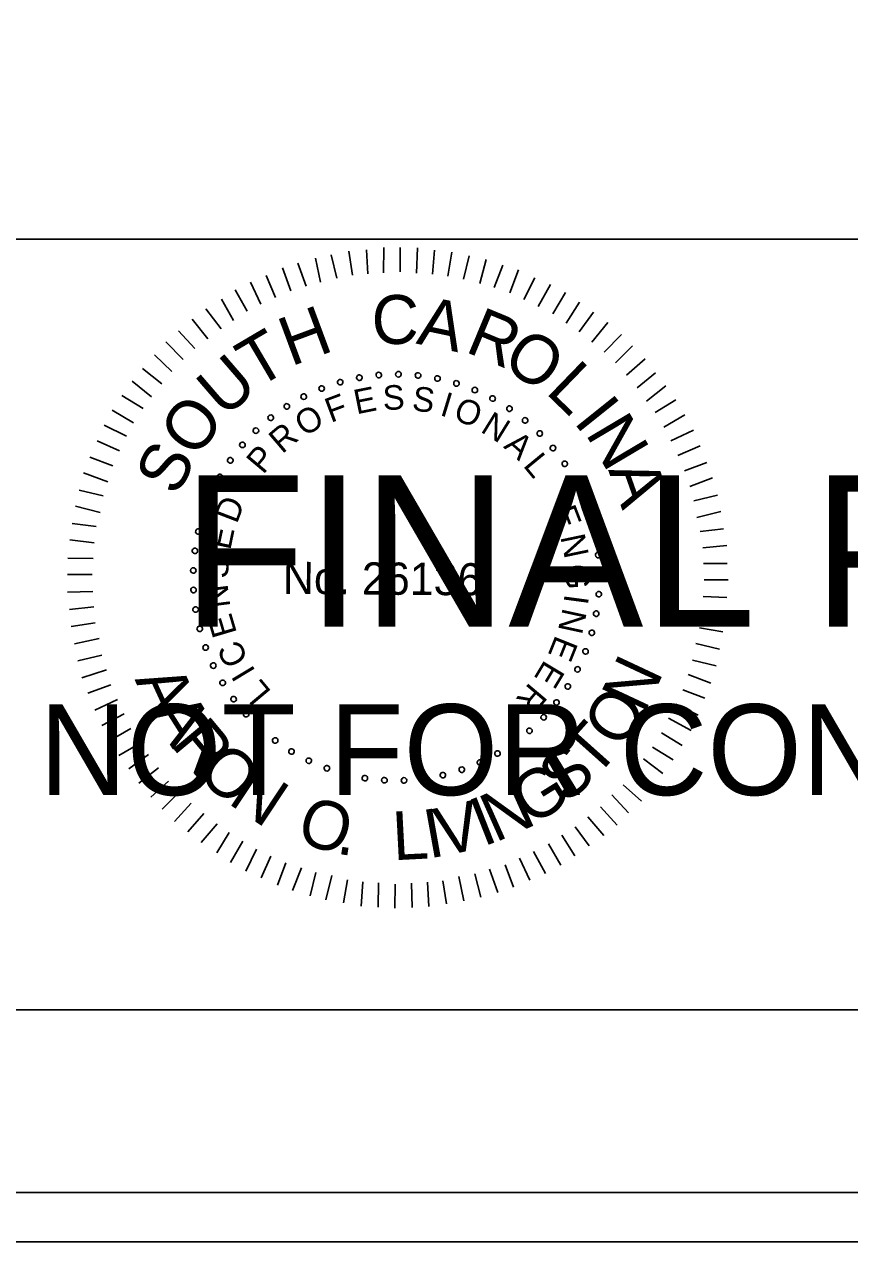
# Model space of a CAD drawing. Extents: x 967 to 1326, y 964 to 3144.
# Drawn here: x 1170.56 to 1189.3, y 1243.72 to 1271.36 of the extents above; entities that cross this region are included whole.
import ezdxf

# ---------------------------------------------------------------- set-up
doc = ezdxf.new("R2010")
doc.units = 0
for name, color, linetype in [('RD_SHT_Bndy', 7, 'Continuous'), ('RD_SHT_IplotShp', 7, 'Continuous'), ('RD_SHT_Misc1', 7, 'Continuous'), ('RD_SHT_Misc2', 7, 'Continuous'), ('RD_Sketch1', 7, 'Continuous')]:
    doc.layers.add(name, color=color, linetype=linetype)

msp = doc.modelspace()

# ---------------------------------------------------------------- linework, layer by layer
at = {"layer": 'RD_SHT_Bndy'}
for p, q in [((996.114, 1266.486), (1323.886, 1266.486)), ((1323.886, 1248.983), (996.114, 1248.983))]:
    msp.add_line(p, q, dxfattribs=at)
at = {"layer": 'RD_SHT_IplotShp'}
for points in [[(967.409, 1243.72), (1326.285, 1243.72), (1326.285, 1463.72), (967.409, 1463.72)], [(988.525, 1244.84), (1326.285, 1244.84), (1326.285, 1462.6), (988.525, 1462.6)]]:
    msp.add_lwpolyline(points, close=True, dxfattribs=at)
at = {"layer": 'RD_SHT_Misc1'}
for p, q in [((1178.01, 1265.663), (1177.93, 1266.209)), ((1178.364, 1265.699), (1178.33, 1266.244)), ((1178.717, 1265.719), (1178.722, 1266.295)), ((1179.093, 1265.739), (1179.098, 1266.292)), ((1179.469, 1265.713), (1179.489, 1266.288)), ((1179.829, 1265.687), (1179.872, 1266.231)), ((1180.174, 1265.646), (1180.271, 1266.19)), ((1176.964, 1265.419), (1176.769, 1265.935)), ((1177.287, 1265.508), (1177.169, 1266.054)), ((1177.657, 1265.597), (1177.53, 1266.128)), ((1180.535, 1265.573), (1180.662, 1266.102)), ((1180.902, 1265.478), (1181.045, 1266.022)), ((1176.264, 1265.156), (1176.053, 1265.657)), ((1176.61, 1265.306), (1176.423, 1265.83)), ((1181.231, 1265.384), (1181.428, 1265.896)), ((1181.584, 1265.265), (1181.78, 1265.786)), ((1175.933, 1265.005), (1175.699, 1265.506)), ((1181.905, 1265.109), (1182.154, 1265.606)), ((1182.226, 1264.953), (1182.506, 1265.45)), ((1175.308, 1264.634), (1175.036, 1265.12)), ((1175.624, 1264.846), (1175.352, 1265.332)), ((1182.562, 1264.789), (1182.85, 1265.27)), ((1175.03, 1264.445), (1174.681, 1264.9)), ((1182.86, 1264.572), (1183.163, 1265.053)), ((1183.158, 1264.378), (1183.484, 1264.828)), ((1174.729, 1264.217), (1174.372, 1264.665)), ((1183.447, 1264.145), (1183.811, 1264.587)), ((1174.435, 1263.997), (1174.062, 1264.399)), ((1183.729, 1263.92), (1184.116, 1264.316)), ((1174.172, 1263.753), (1173.776, 1264.148)), ((1183.98, 1263.672), (1184.368, 1264.061)), ((1173.909, 1263.479), (1173.52, 1263.858)), ((1184.232, 1263.394), (1184.657, 1263.767)), ((1173.684, 1263.197), (1173.242, 1263.546)), ((1184.475, 1263.108), (1184.892, 1263.45)), ((1173.451, 1262.9), (1173.009, 1263.256)), ((1184.687, 1262.807), (1185.128, 1263.156)), ((1173.257, 1262.64), (1172.776, 1262.936)), ((1173.039, 1262.312), (1172.559, 1262.6)), ((1184.885, 1262.544), (1185.355, 1262.832)), ((1185.081, 1262.213), (1185.56, 1262.493)), ((1172.883, 1262.006), (1172.379, 1262.256)), ((1185.24, 1261.904), (1185.756, 1262.145)), ((1172.727, 1261.677), (1172.215, 1261.904)), ((1185.399, 1261.573), (1185.907, 1261.791)), ((1172.571, 1261.333), (1172.051, 1261.53)), ((1185.549, 1261.226), (1186.057, 1261.414)), ((1172.461, 1260.974), (1171.91, 1261.178)), ((1185.669, 1260.865), (1186.185, 1261.06)), ((1172.351, 1260.652), (1171.807, 1260.787)), ((1185.759, 1260.541), (1186.297, 1260.667)), ((1172.286, 1260.276), (1171.727, 1260.419)), ((1185.832, 1260.165), (1186.371, 1260.298)), ((1172.191, 1259.955), (1171.647, 1260.029)), ((1185.906, 1259.842), (1186.436, 1259.906)), ((1172.15, 1259.587), (1171.598, 1259.653)), ((1185.964, 1259.473), (1186.51, 1259.53)), ((1172.124, 1259.234), (1171.548, 1259.239)), ((1185.977, 1259.12), (1186.514, 1259.115)), ((1172.105, 1258.866), (1171.545, 1258.871)), ((1185.997, 1258.751), (1186.542, 1258.747)), ((1172.118, 1258.482), (1171.542, 1258.471)), ((1185.971, 1258.368), (1186.508, 1258.348)), ((1172.138, 1258.136), (1171.585, 1258.072)), ((1185.952, 1258.022), (1186.497, 1257.949)), ((1172.173, 1257.768), (1171.627, 1257.688)), ((1185.888, 1257.655), (1186.417, 1257.566)), ((1172.262, 1257.414), (1171.701, 1257.296)), ((1185.808, 1257.302), (1186.345, 1257.175)), ((1172.321, 1257.037), (1171.774, 1256.911)), ((1185.729, 1256.926), (1186.265, 1256.792)), ((1172.425, 1256.707), (1171.871, 1256.519)), ((1185.634, 1256.597), (1186.146, 1256.401)), ((1172.53, 1256.36), (1172.007, 1256.173)), ((1185.508, 1256.253), (1186.013, 1256.057)), ((1172.681, 1256.029), (1172.165, 1255.788)), ((1172.831, 1255.705), (1172.323, 1255.441)), ((1185.352, 1255.924), (1185.857, 1255.675)), ((1185.188, 1255.603), (1185.7, 1255.33)), ((1172.982, 1255.374), (1172.497, 1255.094)), ((1185.024, 1255.274), (1185.498, 1254.987)), ((1173.194, 1255.042), (1172.709, 1254.762)), ((1184.822, 1254.946), (1185.288, 1254.658)), ((1173.384, 1254.78), (1172.936, 1254.453)), ((1184.62, 1254.687), (1185.055, 1254.353)), ((1173.612, 1254.478), (1173.164, 1254.129)), ((1184.403, 1254.389), (1184.814, 1254.033)), ((1173.832, 1254.177), (1173.437, 1253.812)), ((1184.155, 1254.092), (1184.574, 1253.72)), ((1174.091, 1253.945), (1173.689, 1253.541)), ((1183.899, 1253.864), (1184.28, 1253.454)), ((1174.35, 1253.674), (1173.97, 1253.263)), ((1183.644, 1253.597), (1184.024, 1253.18)), ((1174.64, 1253.442), (1174.275, 1253.022)), ((1174.937, 1253.209), (1174.58, 1252.782)), ((1183.358, 1253.37), (1183.715, 1252.944)), ((1175.212, 1253.014), (1174.932, 1252.549)), ((1182.764, 1252.952), (1183.059, 1252.482)), ((1183.065, 1253.141), (1183.384, 1252.709)), ((1175.525, 1252.812), (1175.245, 1252.331)), ((1182.463, 1252.755), (1182.743, 1252.269)), ((1175.83, 1252.633), (1175.588, 1252.136)), ((1176.159, 1252.477), (1175.94, 1251.98)), ((1181.8, 1252.431), (1182.041, 1251.93)), ((1182.124, 1252.581), (1182.396, 1252.08)), ((1176.503, 1252.321), (1176.307, 1251.816)), ((1176.855, 1252.211), (1176.651, 1251.69)), ((1177.177, 1252.1), (1177.05, 1251.572)), ((1181.122, 1252.175), (1181.31, 1251.652)), ((1181.476, 1252.28), (1181.664, 1251.771)), ((1177.545, 1252.036), (1177.409, 1251.484)), ((1177.897, 1251.933), (1177.808, 1251.412)), ((1178.25, 1251.892), (1178.207, 1251.34)), ((1178.603, 1251.866), (1178.598, 1251.313)), ((1178.978, 1251.84), (1178.974, 1251.295)), ((1179.355, 1251.86), (1179.365, 1251.307)), ((1179.715, 1251.88), (1179.749, 1251.327)), ((1180.061, 1251.915), (1180.149, 1251.393)), ((1180.423, 1252.012), (1180.541, 1251.458)), ((1180.791, 1252.07), (1180.926, 1251.54))]:
    msp.add_line(p, q, dxfattribs=at)
for centre, start, end in [((1178.609, 1263.397), 5.0653, 185.0653), ((1179.055, 1263.414), 359.5268, 179.5268), ((1179.055, 1263.414), 179.5268, 359.5268), ((1179.5, 1263.388), 353.9884, 173.9884), ((1177.312, 1263.091), 21.6807, 201.6807), ((1177.734, 1263.235), 16.1422, 196.1422), ((1177.734, 1263.235), 196.1422, 16.1422), ((1178.168, 1263.337), 10.6038, 190.6038), ((1178.168, 1263.337), 190.6038, 10.6038), ((1178.609, 1263.397), 185.0653, 5.0653), ((1179.5, 1263.388), 173.9884, 353.9884), ((1179.94, 1263.319), 168.4499, 348.4499), ((1179.94, 1263.319), 348.4499, 168.4499), ((1180.372, 1263.208), 162.9114, 342.9114), ((1180.372, 1263.208), 342.9114, 162.9114), ((1176.906, 1262.908), 27.2191, 207.2191), ((1176.906, 1262.908), 207.2191, 27.2191), ((1177.312, 1263.091), 201.6807, 21.6807), ((1180.79, 1263.056), 157.373, 337.373), ((1180.79, 1263.056), 337.373, 157.373), ((1181.193, 1262.864), 151.8345, 331.8345), ((1181.193, 1262.864), 331.8345, 151.8345), ((1176.52, 1262.686), 32.7576, 212.7576), ((1176.52, 1262.686), 212.7576, 32.7576), ((1181.574, 1262.634), 146.2961, 326.2961), ((1181.574, 1262.634), 326.2961, 146.2961), ((1176.156, 1262.428), 38.2961, 218.2961), ((1176.156, 1262.428), 218.2961, 38.2961), ((1181.932, 1262.368), 140.7576, 320.7576), ((1181.932, 1262.368), 320.7576, 140.7576), ((1175.82, 1262.135), 43.8345, 223.8345), ((1175.82, 1262.135), 223.8345, 43.8345), ((1182.263, 1262.069), 135.2191, 315.2191), ((1182.263, 1262.069), 315.2191, 135.2191), ((1175.513, 1261.812), 49.373, 229.373), ((1175.513, 1261.812), 229.373, 49.373), ((1182.563, 1261.74), 129.6807, 309.6807), ((1182.563, 1261.74), 309.6807, 129.6807), ((1175.239, 1261.461), 54.9114, 234.9114), ((1175.239, 1261.461), 234.9114, 54.9114), ((1182.83, 1261.383), 124.1422, 304.1422), ((1182.83, 1261.383), 304.1422, 124.1422), ((1175, 1261.085), 60.4499, 240.4499), ((1175, 1261.085), 240.4499, 60.4499), ((1183.061, 1261.002), 118.6038, 298.6038), ((1183.061, 1261.002), 298.6038, 118.6038), ((1174.798, 1260.687), 65.9884, 245.9884), ((1174.798, 1260.687), 245.9884, 65.9884), ((1183.255, 1260.601), 113.0653, 293.0653), ((1183.255, 1260.601), 293.0653, 113.0653), ((1174.636, 1260.272), 71.5268, 251.5268), ((1174.636, 1260.272), 251.5268, 71.5268), ((1183.408, 1260.182), 107.5268, 287.5268), ((1183.408, 1260.182), 287.5268, 107.5268), ((1174.514, 1259.843), 77.0653, 257.0653), ((1174.514, 1259.843), 257.0653, 77.0653), ((1183.521, 1259.751), 101.9884, 281.9884), ((1183.521, 1259.751), 281.9884, 101.9884), ((1174.435, 1259.405), 82.6038, 262.6038), ((1174.435, 1259.405), 262.6038, 82.6038), ((1183.592, 1259.311), 96.4499, 276.4499), ((1183.592, 1259.311), 276.4499, 96.4499), ((1174.398, 1258.961), 88.1422, 268.1422), ((1174.398, 1258.961), 268.1422, 88.1422), ((1183.619, 1258.866), 90.9114, 270.9114), ((1183.619, 1258.866), 270.9114, 90.9114), ((1174.404, 1258.515), 93.6807, 273.6807), ((1174.404, 1258.515), 273.6807, 93.6807), ((1183.604, 1258.421), 85.373, 265.373), ((1183.604, 1258.421), 265.373, 85.373), ((1174.453, 1258.072), 99.2191, 279.2191), ((1174.453, 1258.072), 279.2191, 99.2191), ((1183.546, 1257.979), 79.8345, 259.8345), ((1183.546, 1257.979), 259.8345, 79.8345), ((1174.545, 1257.636), 104.7576, 284.7576), ((1174.545, 1257.636), 284.7576, 104.7576), ((1183.445, 1257.545), 74.2961, 254.2961), ((1183.445, 1257.545), 254.2961, 74.2961), ((1174.678, 1257.211), 110.2961, 290.2961), ((1174.678, 1257.211), 290.2961, 110.2961), ((1183.303, 1257.122), 68.7576, 248.7576), ((1183.303, 1257.122), 248.7576, 68.7576), ((1174.852, 1256.8), 115.8345, 295.8345), ((1174.852, 1256.8), 295.8345, 115.8345), ((1183.121, 1256.716), 63.2191, 243.2191), ((1183.121, 1256.716), 243.2191, 63.2191), ((1175.065, 1256.409), 121.373, 301.373), ((1175.065, 1256.409), 301.373, 121.373), ((1182.9, 1256.328), 57.6807, 237.6807), ((1182.9, 1256.328), 237.6807, 57.6807), ((1175.314, 1256.039), 126.9114, 306.9114), ((1175.314, 1256.039), 306.9114, 126.9114), ((1182.643, 1255.964), 52.1422, 232.1422), ((1182.643, 1255.964), 232.1422, 52.1422), ((1175.598, 1255.696), 132.4499, 312.4499), ((1175.598, 1255.696), 312.4499, 132.4499), ((1182.353, 1255.627), 46.6038, 226.6038), ((1175.914, 1255.381), 137.9884, 317.9884), ((1175.914, 1255.381), 317.9884, 137.9884), ((1182.353, 1255.627), 226.6038, 46.6038), ((1176.258, 1255.099), 143.5268, 323.5268), ((1176.258, 1255.099), 323.5268, 143.5268), ((1182.03, 1255.319), 41.0653, 221.0653), ((1182.03, 1255.319), 221.0653, 41.0653), ((1176.629, 1254.851), 149.0653, 329.0653), ((1176.629, 1254.851), 329.0653, 149.0653), ((1181.305, 1254.803), 29.9884, 209.9884), ((1181.68, 1255.043), 35.5268, 215.5268), ((1181.68, 1255.043), 215.5268, 35.5268), ((1177.021, 1254.639), 154.6038, 334.6038), ((1177.021, 1254.639), 334.6038, 154.6038), ((1180.908, 1254.6), 24.4499, 204.4499), ((1180.908, 1254.6), 204.4499, 24.4499), ((1181.305, 1254.803), 209.9884, 29.9884), ((1177.432, 1254.467), 160.1422, 340.1422), ((1177.432, 1254.467), 340.1422, 160.1422), ((1177.858, 1254.335), 165.6807, 345.6807), ((1177.858, 1254.335), 345.6807, 165.6807), ((1178.294, 1254.245), 351.2191, 171.2191), ((1179.627, 1254.232), 7.8345, 187.8345), ((1180.065, 1254.313), 13.373, 193.373), ((1180.065, 1254.313), 193.373, 13.373), ((1180.494, 1254.436), 18.9114, 198.9114), ((1180.494, 1254.436), 198.9114, 18.9114), ((1178.294, 1254.245), 171.2191, 351.2191), ((1178.737, 1254.198), 356.7576, 176.7576), ((1178.737, 1254.198), 176.7576, 356.7576), ((1179.183, 1254.193), 2.2961, 182.2961), ((1179.183, 1254.193), 182.2961, 2.2961), ((1179.627, 1254.232), 187.8345, 7.8345)]:
    msp.add_arc(centre, 0.0627, start, end, dxfattribs=at)
at = {"layer": 'RD_Sketch1'}
msp.add_lwpolyline([(967.409, 1243.72), (1326.285, 1243.72), (1326.285, 1463.72), (967.409, 1463.72)], close=True, dxfattribs=at)

# ---------------------------------------------------------------- texts
at = {"layer": 'RD_SHT_Misc1'}
for s, height, rotation, p in [('C', 1.11, 359.5482, (1178.442, 1264.108)), ('A', 1.11, 348.1981, (1179.439, 1264.115)), ('H', 1.11, 20.3637, (1176.614, 1263.587)), ('R', 1.11, 337.4344, (1180.541, 1263.937)), ('T', 1.11, 30.4992, (1175.828, 1263.072)), ('O', 1.108, 326.5869, (1181.366, 1263.609)), ('U', 1.11, 40.8022, (1175.102, 1262.403)), ('L', 1.11, 315.9488, (1182.373, 1263.003)), ('E', 0.557, 11.4103, (1178.103, 1262.503)), ('S', 0.557, 2.208, (1178.709, 1262.601)), ('S', 0.557, 352.6608, (1179.346, 1262.599)), ('F', 0.557, 20.6127, (1177.52, 1262.309)), ('I', 0.557, 343.1136, (1179.975, 1262.491)), ('O', 0.557, 338.4392, (1180.274, 1262.401)), ('I', 1.11, 308.6613, (1183.011, 1262.338)), ('O', 1.11, 52.0267, (1174.435, 1261.474)), ('O', 0.557, 30.8477, (1176.917, 1261.987)), ('N', 0.557, 328.2042, (1180.896, 1262.12)), ('N', 1.11, 300.7037, (1183.285, 1262.075)), ('R', 0.557, 40.3949, (1176.415, 1261.594)), ('A', 0.557, 318.657, (1181.424, 1261.762)), ('S', 1.108, 63.2511, (1174.029, 1260.619)), ('P', 0.557, 49.9421, (1175.985, 1261.124)), ('L', 0.557, 309.4546, (1181.869, 1261.339)), ('A', 1.11, 289.4792, (1183.814, 1261.243)), ('D', 0.557, 69.0364, (1175.386, 1260.003)), ('E', 0.557, 291.049, (1182.53, 1260.307)), ('E', 0.557, 78.2388, (1175.238, 1259.407)), ('N', 0.557, 281.8466, (1182.728, 1259.726)), ('S', 0.557, 87.786, (1175.187, 1258.772)), ('No. 26136', 0.7311, 359.5268, (1176.429, 1258.43)), ('G', 0.557, 272.2995, (1182.833, 1259.097)), ('N', 0.557, 97.3332, (1175.242, 1258.137)), ('I', 0.557, 262.4084, (1182.83, 1258.437)), ('E', 0.557, 106.5355, (1175.394, 1257.541)), ('N', 0.557, 257.7339, (1182.789, 1258.127)), ('C', 0.557, 116.4266, (1175.661, 1256.938)), ('E', 0.557, 248.1867, (1182.628, 1257.511)), ('I', 0.557, 121.1011, (1175.823, 1256.67)), ('E', 0.557, 238.9844, (1182.378, 1256.949)), ('N', 1.105, 64.8922, (1184.632, 1255.684)), ('A', 1.105, 294.7297, (1173.062, 1256.486)), ('L', 0.557, 129.9595, (1176.187, 1256.204)), ('R', 0.557, 229.782, (1182.041, 1256.435)), ('A', 1.105, 302.2892, (1173.414, 1255.72)), ('O', 1.105, 56.2059, (1184.102, 1254.874)), ('R', 1.105, 309.8487, (1173.865, 1255.007)), ('T', 1.105, 48.2685, (1183.515, 1254.211)), ('O', 1.105, 317.7861, (1174.434, 1254.33)), ('S', 1.105, 40.3311, (1182.842, 1253.636)), ('N', 1.105, 326.4725, (1175.158, 1253.686)), ('G', 1.105, 32.0198, (1182.059, 1253.14)), ('N', 1.105, 24.0824, (1181.252, 1252.776)), ('O', 1.105, 342.3472, (1176.697, 1252.82)), ('V', 1.105, 12.7741, (1180.033, 1252.457)), ('I', 1.105, 21.4605, (1180.976, 1252.681)), ('L', 1.105, 2.9677, (1178.943, 1252.379)), ('I', 1.105, 10.1523, (1179.743, 1252.418)), ('.', 1.105, 351.0336, (1177.623, 1252.536))]:
    msp.add_text(s, height=height, rotation=rotation, dxfattribs=at).set_placement(p)
at = {"layer": 'RD_SHT_Misc2'}
for s, height, p in [('FINAL PLANS', 3.4375, (1174.145, 1257.685)), ('NOT FOR CONSTRUCTION', 2.0625, (1170.901, 1253.86))]:
    msp.add_text(s, height=height, dxfattribs=at).set_placement(p)

doc.saveas('drawing.dxf')
